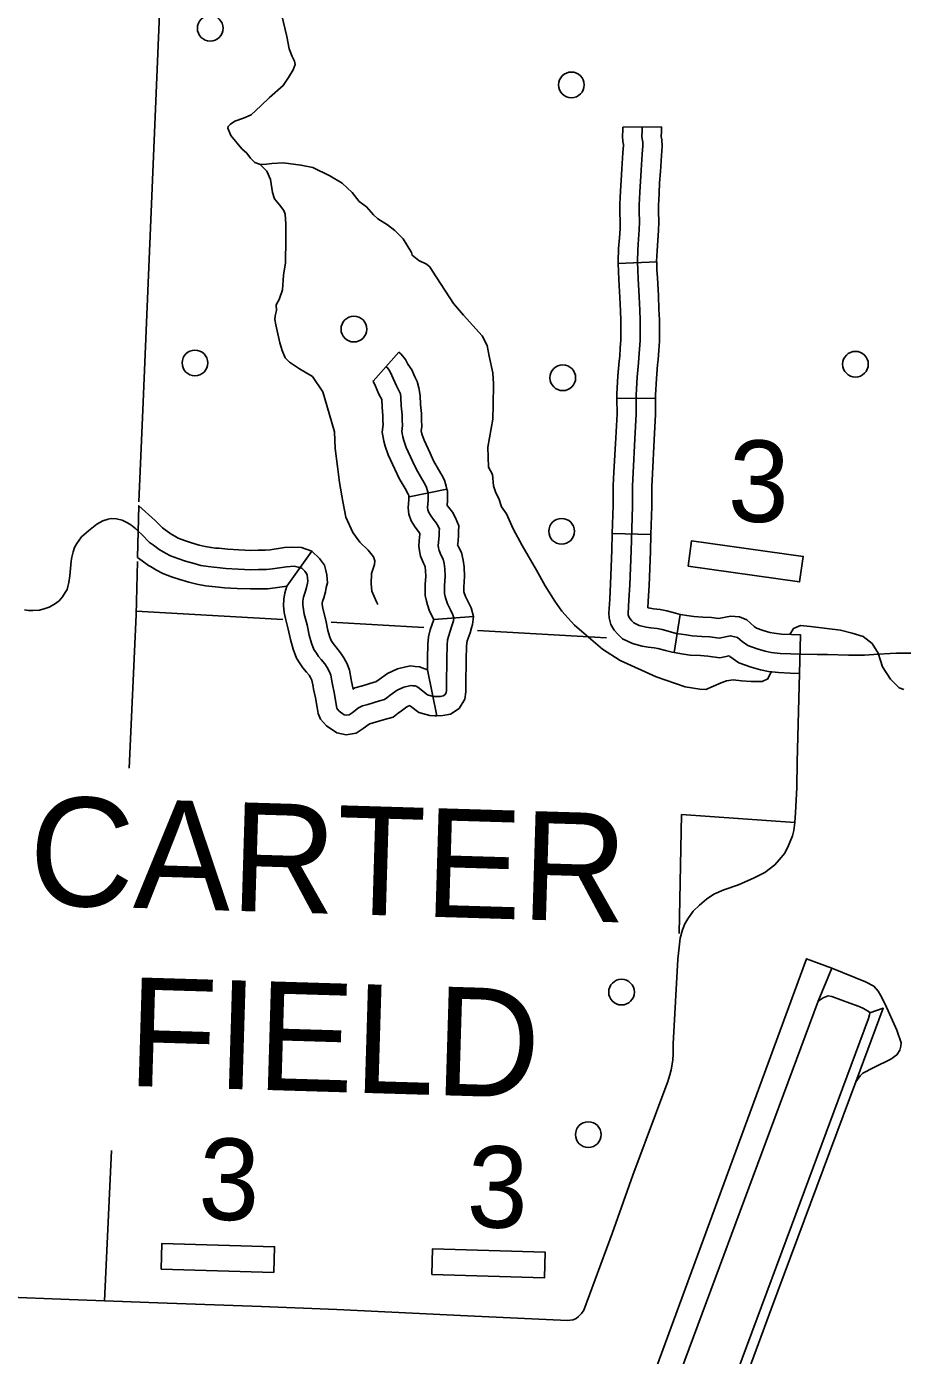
# Model space of a CAD drawing. Extents: x 653372 to 905732, y 627442 to 787275.
# Drawn here: x 689902 to 693304, y 750128 to 755293 of the extents above; entities that cross this region are included whole.
import ezdxf

# ---------------------------------------------------------------- set-up
doc = ezdxf.new("R2010")
doc.units = 0
for name, color, linetype in [('31', 7, 'Continuous'), ('32', 7, 'Continuous'), ('33', 7, 'Continuous'), ('35', 7, 'Continuous'), ('5', 7, 'Continuous'), ('56', 7, 'Continuous'), ('57', 7, 'Continuous'), ('6', 7, 'Continuous')]:
    doc.layers.add(name, color=color, linetype=linetype)

msp = doc.modelspace()

# ---------------------------------------------------------------- linework, layer by layer
at = {"layer": '31'}
msp.add_line((690913.4, 753117.6), (691010.3, 753253.9), dxfattribs=at)
for points in [[(690460.4, 753322.2), (690458.5, 753323.3), (690440.5, 753336.5), (690430, 753344.4), (690402.2, 753372.7), (690338.1, 753430.3), (690333.1, 753229.5)], [(691108.1, 752641.3), (691107.5, 752642.7), (691105.4, 752657.7), (691097.7, 752697.9), (691088.8, 752741.5), (691083.7, 752771.2), (691079, 752784.1), (691069.3, 752801), (691060.8, 752815.3), (691046.5, 752832.3), (691035.8, 752844.5), (691028.1, 752857.1), (691017.9, 752871.9), (691009.3, 752895.9), (691000, 752927.7), (690991.9, 752967.7), (690980.8, 753008.8), (690977.5, 753026.4), (690975.1, 753045.1), (690975.9, 753059.6), (690978.1, 753074.8), (690984.6, 753094.2), (690989.8, 753112.7), (690992.9, 753129.1), (690995.3, 753137.5), (690994, 753150.3), (690991.7, 753160.6), (690990.2, 753166.6), (690983.7, 753175.7), (690971.7, 753187.1), (690957.4, 753191.4), (690941.3, 753194.8), (690911.5, 753193.2), (690857.7, 753185), (690833.8, 753182.3), (690802.8, 753182), (690772.9, 753181.6), (690723.6, 753183.5), (690676.9, 753186.2), (690642.2, 753190.2), (690629.2, 753191), (690608, 753193.4), (690579.7, 753198.5), (690552.7, 753205.2), (690520.2, 753215.1), (690490.4, 753225), (690461.4, 753236), (690442.5, 753245.5), (690417, 753260.7), (690395.8, 753276.3), (690380.4, 753287.8), (690350.3, 753318.5), (690335.6, 753331.7)], [(691010.3, 753253.9), (690970.5, 753267.5), (690932.4, 753269.4), (690903.8, 753267.9), (690847.9, 753259.4), (690829.2, 753257.3), (690801.9, 753257), (690773.9, 753256.6), (690727.2, 753258.4), (690683.4, 753260.9), (690648.9, 753264.9), (690635.6, 753265.8), (690618.8, 753267.6), (690595.5, 753271.8), (690572.8, 753277.5), (690542.9, 753286.6), (690515.5, 753295.6), (690491.7, 753304.7), (690478.7, 753311.3), (690460.4, 753322.2)], [(690383.5, 753193.4), (690375.6, 753198.2), (690351.2, 753216), (690333.1, 753229.5)], [(691010.3, 753253.9), (691040.5, 753225.1), (691059.4, 753198.7), (691064.7, 753177.8), (691068.1, 753162.2), (691071.3, 753130.9), (691066, 753112), (691063, 753095.7), (691056.3, 753072), (691051.4, 753057.4), (691050.6, 753052.1), (691050.4, 753047.7), (691051.6, 753038.1), (691053.9, 753025.5), (691064.9, 752984.9), (691072.9, 752945.7), (691080.6, 752919.1), (691085.2, 752906.4), (691091, 752898), (691096.4, 752889.1), (691103.4, 752881.2), (691122.1, 752858.9), (691134.1, 752838.9), (691147.3, 752815.9), (691156.5, 752790.6), (691162.5, 752755.3), (691164.2, 752747)], [(690913.4, 753117.6), (690867.5, 753110.6), (690838.4, 753107.4), (690803.7, 753107), (690771.9, 753106.6), (690720, 753108.6), (690670.5, 753111.4), (690635.6, 753115.5), (690622.7, 753116.3), (690597.2, 753119.1), (690563.9, 753125.1), (690532.6, 753132.9), (690497.6, 753143.6), (690465.2, 753154.3), (690431, 753167.3), (690406.4, 753179.8), (690383.5, 753193.4)], [(691017.2, 752717.1), (691015.1, 752727.7), (691010.9, 752751.9), (691010.8, 752752.3), (691004.6, 752763.1), (690999.5, 752771.6), (690989.6, 752783.4), (690975.1, 752799.9), (690965.2, 752816.2), (690950.6, 752837.3), (690937.9, 752872.8), (690927.1, 752909.7), (690918.8, 752950.4), (690907.6, 752992.1), (690903.4, 753014.6), (690899.8, 753042.6), (690901.2, 753067.1), (690904.8, 753092.2), (690913.4, 753117.6)], [(691164.2, 752747), (691170.2, 752717.8), (691177.7, 752722.1), (691207, 752730.1), (691252.5, 752744.1), (691258.4, 752745.6), (691271.4, 752754.9), (691304.6, 752778.5), (691343, 752796), (691392.5, 752808.2), (691412, 752805.2), (691429, 752803.8), (691459.1, 752792), (691495.4, 752613.4)], [(691495.4, 752613.4), (691488.6, 752613.4), (691469.1, 752614.5), (691426.3, 752626), (691394, 752650.7), (691391.1, 752653.1), (691379.8, 752648), (691358.7, 752632.9), (691346.2, 752623.9), (691326.1, 752608), (691292.9, 752599.6), (691248.7, 752586), (691235.6, 752582.4), (691233.1, 752581), (691209.5, 752563.7), (691182.2, 752546.1), (691144, 752540), (691106.8, 752547), (691066.9, 752574.7), (691044, 752600.7), (691034.6, 752622.3), (691031.4, 752645.4), (691024.1, 752683.3), (691017.2, 752717.1)], [(691492.6, 752688.3), (691481, 752688.9), (691460.1, 752694.6), (691441.3, 752708.9), (691427.6, 752720.8), (691418.2, 752727.5), (691411.8, 752730), (691403.2, 752730.7), (691395.9, 752731.8), (691367.7, 752724.9), (691342.2, 752713.3), (691315, 752693.9), (691301, 752683.8), (691292.1, 752676.7), (691272.7, 752671.8), (691227.9, 752658), (691206.6, 752652.3), (691192.2, 752644), (691166.9, 752625.5), (691154.7, 752617.6), (691145.1, 752616.1), (691136.4, 752617.7), (691117.1, 752631.1), (691108.1, 752641.3)]]:
    msp.add_lwpolyline(points, dxfattribs=at)
at = {"layer": '32'}
for p, q in [((692218.7, 754901.7), (692368.7, 754902.3)), ((692199.8, 754372.1), (692349.7, 754378.1)), ((691248.4, 753914.8), (691347.6, 754027.4)), ((692195.1, 753847.3), (692345.1, 753848.7)), ((691388, 753464.2), (691534.9, 753494.5)), ((692177.2, 753322.6), (692327.1, 753318.1)), ((691483.7, 752987.6), (691637.7, 752999.6)), ((692418.2, 752859.1), (692441.3, 753007.3))]:
    msp.add_line(p, q, dxfattribs=at)
for points in [[(692218.7, 754901.7), (692218.8, 754890.3), (692216.9, 754866), (692218.4, 754845.5), (692220.7, 754834.2), (692220.9, 754830.3), (692218.7, 754801.4), (692214.9, 754739.6), (692211.5, 754694.2), (692209.8, 754653.7), (692208, 754626.4), (692206.7, 754604.1), (692206.4, 754572.6), (692207.6, 754532.4), (692207.3, 754506.2), (692204.8, 754471), (692202, 754429.7), (692199.5, 754380.1), (692199.8, 754372.1)], [(692293.7, 754902), (692293.8, 754887.6), (692292.1, 754865.8), (692292.8, 754855.8), (692295.4, 754843.4), (692296, 754828.9), (692293.5, 754796.2), (692289.7, 754734.5), (692286.4, 754689.9), (692284.7, 754649.7), (692282.8, 754621.9), (692281.7, 754601.6), (692281.4, 754573.3), (692282.6, 754533), (692282.2, 754503.1), (692279.6, 754465.9), (692276.9, 754425.2), (692274.6, 754379.6), (692276, 754344.3), (692277.5, 754313.2), (692281.9, 754242.6), (692283.8, 754190.9), (692285.6, 754151.1), (692285.3, 754109.4), (692285.2, 754072.1), (692283.2, 754038.2), (692280.7, 754005.2), (692278.6, 753985.2), (692274, 753929.7), (692269.9, 753861.8), (692270.6, 753786.2), (692265.3, 753690.4), (692258.3, 753557.5), (692256.3, 753506.9), (692255.4, 753428.9), (692250.2, 753254.8), (692245.3, 753123.1), (692242, 753063.1), (692239, 753012.5), (692239.3, 753006.6), (692241.5, 752998.5), (692246.2, 752990.5), (692253.4, 752982.3), (692261.2, 752974.6), (692281.2, 752965.1), (692308.6, 752958.3), (692326.4, 752955.3), (692351.6, 752952.5), (692371.3, 752948.5), (692403.8, 752939.5), (692425, 752933.9), (692464.6, 752927.8), (692487.3, 752924.6), (692524.5, 752922.5), (692555.7, 752920.6), (692592.3, 752915.5), (692637, 752924.7), (692663.8, 752918.3), (692681.2, 752902.4), (692703.6, 752886.8), (692740.2, 752874.3), (692770.7, 752865), (692794.9, 752860.3), (692829, 752856.3), (692870.7, 752854.5), (692906.9, 752853.4)], [(692368.7, 754902.3), (692368.8, 754884.9), (692367.4, 754865.9), (692370.1, 754852.5), (692371.1, 754827.6), (692368.3, 754791.1), (692364.5, 754729.3), (692361.2, 754685.5), (692359.5, 754645.6), (692357.7, 754617.4), (692356.7, 754599.1), (692356.4, 754574), (692357.7, 754533.7), (692357.2, 754499.9), (692354.5, 754460.8), (692351.8, 754420.8), (692349.6, 754379.2), (692349.7, 754378.1)], [(692199.8, 754372.1), (692201.1, 754340.9), (692202.6, 754309.1), (692206.9, 754238.9), (692208.8, 754187.8), (692210.6, 754149.6), (692210.3, 754109.7), (692210.2, 754074.5), (692208.3, 754043.2), (692206, 754011.9), (692203.9, 753992.2), (692199.1, 753935), (692194.9, 753863.6), (692195.1, 753847.3)], [(692349.7, 754378.1), (692350.9, 754347.7), (692352.4, 754317.4), (692356.8, 754246.3), (692358.7, 754193.9), (692360.6, 754152.5), (692360.3, 754109), (692360.2, 754069.8), (692358, 754033.1), (692355.4, 753998.5), (692353.3, 753978.1), (692348.8, 753924.3), (692344.9, 753859.9), (692345.1, 753848.7)], [(691347.6, 754027.4), (691357.8, 754018.8), (691373.7, 753998.6), (691383.4, 753980.5), (691398.6, 753958.4), (691410.5, 753931.4), (691418.8, 753912.8), (691426.5, 753888.3), (691431.3, 753858.7), (691432.7, 753823.4), (691435.8, 753788.3), (691436.6, 753764.5), (691437, 753738.4), (691435.2, 753721.6), (691436.5, 753714.3), (691438.7, 753706.3), (691446.3, 753685.4), (691469.5, 753634.7), (691483.1, 753604.9), (691502.2, 753571.6), (691515.3, 753548.9), (691525.7, 753529.7), (691532.5, 753506.2), (691534.9, 753494.5)], [(691299.2, 753970.1), (691303.6, 753966.3), (691310.7, 753957.4), (691315.9, 753947.6), (691325.8, 753925.3), (691338.6, 753896.1), (691349, 753876.1), (691354.2, 753865.4), (691356.5, 753851.2), (691357.8, 753818.6), (691360.9, 753783.7), (691361.6, 753762.6), (691361.9, 753742), (691359.4, 753718.7), (691363.4, 753697.7), (691367.1, 753683.8), (691376.8, 753657), (691401.3, 753603.5), (691416.3, 753570.6), (691437.2, 753534.2), (691449.9, 753512.3), (691455.9, 753501.1), (691459.7, 753488.2), (691461.7, 753478.5), (691461.8, 753452.4), (691460, 753423.9), (691461.1, 753414.7), (691464.9, 753403.6), (691473.2, 753389.6), (691483.3, 753376.9), (691493.5, 753363.8), (691500.9, 753350.7), (691505.6, 753339.1), (691505.3, 753330.9), (691505.3, 753316.2), (691502.2, 753287), (691501.4, 753275.6), (691502.5, 753266.8), (691504.5, 753256.2), (691511.7, 753239), (691520.4, 753222.3), (691524, 753205.7), (691527, 753185), (691528.5, 753156.1), (691526, 753118.4), (691525.1, 753105.6), (691525.6, 753089.6), (691527.9, 753077.1), (691530.9, 753067.9), (691537.2, 753049.4), (691548.4, 753026.1), (691558.3, 753006.6), (691561.6, 752994.1), (691560.4, 752983.2), (691553.2, 752959.1), (691542.2, 752926.4), (691537.5, 752908.7), (691536, 752888.6), (691534.4, 752834.4), (691533.7, 752735.9), (691533, 752712.6), (691531.8, 752703), (691527.5, 752695.8), (691520, 752691), (691509.9, 752689), (691492.6, 752688.3)], [(691248.4, 753914.8), (691248.4, 753914.8), (691257.2, 753895.1), (691271, 753863.6), (691281.8, 753842.9), (691283, 753813.8), (691286, 753779.1), (691286.7, 753760.7), (691286.9, 753745.5), (691283.7, 753715.7), (691290.2, 753681), (691295.4, 753661.3), (691307.3, 753628.5), (691333.1, 753572.3), (691349.6, 753536.2), (691372.2, 753496.8), (691384.4, 753475.6), (691386.1, 753472.5), (691386.8, 753470.2), (691388, 753464.2)], [(692195.1, 753847.3), (692195.6, 753788), (692190.4, 753694.4), (692183.4, 753560.9), (692181.3, 753508.8), (692180.5, 753430.5), (692177.2, 753322.6)], [(692345.1, 753848.7), (692345.7, 753784.5), (692340.2, 753686.3), (692333.2, 753554), (692331.3, 753505), (692330.4, 753427.4), (692327.1, 753318.1)], [(691534.9, 753494.5), (691536.6, 753486.3), (691536.8, 753450.2), (691535.6, 753431.6), (691542.3, 753423.3), (691556.1, 753405.4), (691568.6, 753383.4), (691581, 753352.6), (691580.3, 753329.8), (691580.3, 753312.2), (691576.9, 753280.3), (691576.7, 753277.9), (691579.7, 753270.9), (691591.5, 753247.9), (691597.8, 753219.2), (691601.8, 753192.3), (691603.6, 753155.4), (691600.8, 753113.5), (691600.2, 753104.2), (691600.4, 753097.7), (691600.8, 753095.6), (691602.1, 753091.3), (691606.7, 753077.9), (691615.6, 753059.4), (691628.8, 753033.5), (691637.7, 752999.6), (691634.2, 752968.2), (691630.3, 752955.2)], [(691386.7, 753470.6), (691386.8, 753454.5), (691384.7, 753421.7), (691387.6, 753397.9), (691396.4, 753372), (691411.3, 753346.8), (691424.4, 753330.5), (691430.3, 753322.8), (691430.3, 753320.2), (691427.5, 753293.6), (691426, 753273.4), (691428.4, 753255.2), (691432.2, 753234.5), (691443.8, 753207.2), (691449.2, 753196.6), (691450.2, 753192.2), (691452.3, 753177.7), (691453.3, 753156.7), (691451.1, 753123.4), (691450.1, 753107.1), (691450.7, 753081.5), (691455.1, 753058.7), (691459.6, 753044.5), (691467.6, 753020.9), (691483.7, 752987.6)], [(692177.2, 753322.6), (692175.3, 753257.3), (692170.3, 753126.6), (692167.1, 753067.4), (692163.8, 753012.8), (692164.8, 752994.3), (692171.9, 752969.1), (692185.2, 752946.3), (692198.8, 752930.9), (692217.3, 752912.4), (692255.9, 752894.1), (692293.3, 752884.8), (692316, 752881), (692339.9, 752878.4), (692353.8, 752875.5), (692384.3, 752867.1), (692409.6, 752860.4), (692418.3, 752859.1)], [(692327.1, 753318.1), (692325.2, 753252.2), (692320.2, 753119.6), (692316.9, 753058.8), (692315.4, 753033.9), (692323.9, 753031.8), (692336.7, 753029.6), (692363.3, 753026.7), (692388.9, 753021.4), (692423.4, 753012), (692440.4, 753007.4), (692441.3, 753007.3)], [(691483.7, 752987.6), (691470.3, 752948), (691463.3, 752921.2), (691461.1, 752892.6), (691459.4, 752835.8), (691459.1, 752792)], [(692441.3, 753007.3), (692475.5, 753002), (692494.6, 752999.3), (692528.9, 752997.4), (692563.2, 752995.3), (692589.8, 752991.6), (692638.2, 753001.4), (692671.5, 752998.9), (692700.1, 752986.8), (692728.2, 752961.1), (692737.8, 752954.4), (692763.4, 752945.7), (692788.9, 752937.8), (692806.4, 752934.4), (692835, 752931.1), (692873.4, 752929.5), (692908.1, 752928.4), (692904.2, 752778.5)], [(691630.3, 752955.2), (691624.7, 752936.4), (691614.1, 752904.9), (691611.8, 752896.3), (691610.9, 752884.6), (691609.4, 752833), (691608.7, 752734.5), (691607.9, 752706.8), (691604.2, 752677.9), (691582.7, 752642.2), (691548.5, 752620.1), (691518.6, 752614.3), (691495.4, 752613.4)], [(692418.2, 752859.1), (692453.6, 752853.6), (692480, 752849.9), (692520, 752847.6), (692548.2, 752845.9), (692594.7, 752839.5), (692630.9, 752846.8), (692634.3, 752843.7), (692669.4, 752819.3), (692717.1, 752803), (692752.5, 752792.1), (692783.4, 752786.1), (692823.1, 752781.4), (692868, 752779.6), (692904.2, 752778.5)]]:
    msp.add_lwpolyline(points, dxfattribs=at)
at = {"layer": '33'}
for points in [[(689894.9, 753025.4), (689910.1, 753022.8), (689926.7, 753022.7), (689952.5, 753024.9), (689974.7, 753030.6), (689990.2, 753036.5), (690011.4, 753047.4), (690028.8, 753060.9), (690041.6, 753075.8), (690052.3, 753092.5), (690059.9, 753105), (690063.1, 753115.6), (690066.2, 753132.1), (690069.9, 753157.9), (690075.5, 753215.1), (690078.1, 753230.4), (690082.9, 753250.4), (690088.1, 753267.6), (690097.9, 753283.5), (690116.2, 753309.8), (690142.8, 753333.2), (690175, 753358.2), (690198.3, 753371.1), (690219, 753378.5), (690231.4, 753380.7), (690251.4, 753379.3), (690274.2, 753373.9), (690294.8, 753364.3), (690307.7, 753355.9), (690326.3, 753340), (690335.6, 753331.7)], [(692906.9, 752853.4), (692973.4, 752852.4), (693013.2, 752851.8), (693094.2, 752849.7), (693156.7, 752849.8), (693211, 752852.9), (693256.5, 752855.5), (693281.3, 752857.1), (693309.6, 752857), (693346.5, 752856.7), (693375.2, 752855.9), (693414.8, 752854.3), (693483.9, 752850.6), (693508.6, 752849.9), (693540.5, 752850.5)], [(692611.1, 751936.9), (692667.6, 751956.9), (692728.6, 751983.7), (692769.8, 752004.9), (692808.5, 752034.5), (692825.9, 752053.6), (692847, 752080.3), (692861.1, 752109.9), (692876.9, 752146.6), (692882.5, 752167.4), (692886.9, 752199.4), (692889.4, 752236.5), (692893.8, 752335), (692895.4, 752434.6), (692904.2, 752778)], [(689805.2, 750355.2), (690068, 750345.2), (690412.6, 750332.1), (690815.2, 750317.2), (691107.3, 750305.6), (691615.2, 750281.3), (692003.2, 750263.3), (692024.9, 750266.2), (692037, 750270.7), (692046.3, 750278.8), (692057.8, 750290.4), (692066.6, 750303.4), (692176.3, 750601.8), (692256.6, 750827.6), (692349.4, 751074), (692392.8, 751192.4), (692400.6, 751218.1), (692406.1, 751238.2), (692410.2, 751259.1), (692412.8, 751276.5), (692413.5, 751298.9), (692414, 751338.7), (692432.3, 751667.9), (692440.3, 751748.8), (692449.7, 751781.4), (692459.5, 751804.9), (692471.3, 751824.9), (692491, 751853.7), (692515.5, 751878.1), (692542.8, 751901.1), (692572.1, 751920.5), (692611.1, 751936.9)]]:
    msp.add_lwpolyline(points, dxfattribs=at)
at = {"layer": '35'}
for points in [[(690893.6, 755335.6), (690913.3, 755254.6), (690922.8, 755206.2), (690933.8, 755176.7), (690942.7, 755158.3), (690945.4, 755144.8), (690937.7, 755123.8), (690920.3, 755094.3), (690899.6, 755063.4), (690846.2, 755016.5), (690812.1, 754984.4), (690774.8, 754950.1), (690744.5, 754936), (690711.8, 754925.1), (690694.1, 754913.8), (690685.2, 754904.6), (690683.4, 754897.6), (690696, 754869.6), (690737.8, 754817.9), (690757.7, 754800), (690772.1, 754780.6), (690789, 754764.3), (690806.9, 754758.3), (690823.4, 754756.2), (690855.1, 754760.8), (690900.8, 754762.5), (690967.6, 754754.2), (691014.6, 754744.9), (691080.6, 754712.2), (691128.7, 754684.1), (691167, 754647.5), (691193.5, 754612.8), (691222.1, 754592.2), (691249.5, 754561.4), (691266, 754544.7), (691304.8, 754521.5), (691333.3, 754500.1), (691365.4, 754467.6), (691396.9, 754413.9), (691400.5, 754403.5), (691425.9, 754383), (691455.5, 754368.7), (691469.2, 754358.1)], [(690810.8, 754754.6), (690835.4, 754730.8), (690850, 754697.6), (690858.1, 754647.6), (690864.8, 754622.9), (690884.2, 754599.2), (690901.4, 754577.9), (690906.1, 754563.7), (690908.7, 754524.2), (690909.9, 754466.7), (690907.9, 754373.9), (690899.8, 754326.5), (690895.8, 754269.4), (690882.8, 754231.2), (690871.8, 754210.7), (690872.6, 754189.1), (690868.3, 754168.4), (690866.4, 754154.4), (690870.2, 754133.4), (690885.9, 754063.1), (690894.7, 754033.1), (690906.5, 754005.3), (690923, 753988.4), (690962.1, 753961.7), (691013.3, 753932)], [(691469.2, 754358.1), (691478.4, 754341.6), (691560, 754216.1), (691599.6, 754170.5), (691672.5, 754090.5), (691691.5, 754053.5), (691699, 754011.8), (691713.4, 753947.3), (691715.9, 753904.5), (691714.7, 753821.7), (691713, 753766.5), (691693.4, 753657.8), (691696.1, 753579.8), (691711.6, 753551.7), (691715.3, 753507.6), (691724.5, 753479.7), (691736.4, 753458), (691747.2, 753426.4), (691765.9, 753398.5), (691792.2, 753339.8), (691826.7, 753276), (691883.1, 753180.3), (691916.4, 753119), (691953.9, 753059.5), (691981.8, 753020), (692030.5, 752966.3), (692139.1, 752873.1), (692208.1, 752828.1), (692347.4, 752764.6)], [(691013.3, 753932), (691053.1, 753872.8), (691078, 753788.1), (691098.2, 753717.6), (691101.5, 753652.8), (691109.8, 753583), (691117.5, 753520.3), (691130.2, 753447.1), (691142.5, 753385.1), (691169.7, 753326.3), (691196.8, 753288.3), (691228.5, 753257.6), (691250, 753231.4), (691254.8, 753216.4), (691254.3, 753201.6), (691241.4, 753166.3), (691240.2, 753126.2), (691243.8, 753097.8), (691261.1, 753056.4), (691266.8, 753046.4)], [(692866.6, 752929.7), (692881.2, 752953), (692907.9, 752964.9), (692947.1, 752960.9), (693063.2, 752946.9), (693109.3, 752934.4), (693151.9, 752921.4), (693186.3, 752895), (693209.8, 752857)], [(693209.8, 752857), (693219.4, 752828), (693226.4, 752804.5), (693258, 752755.8)], [(692347.4, 752764.6), (692460.7, 752725.7), (692517.4, 752716.9), (692540.1, 752715.4)], [(692540.1, 752715.4), (692600, 752741.2), (692621, 752750), (692646.2, 752753.6), (692678.8, 752750.1), (692716.3, 752747.1), (692759.7, 752747.5), (692781.5, 752757.6), (692794.4, 752784)], [(693258, 752755.8), (693291.4, 752722.5), (693310, 752716.2)]]:
    msp.add_lwpolyline(points, dxfattribs=at)
at = {"layer": '5'}
for points in [[(690897.6, 752987.9), (690328.4, 753020.4)], [(691445.8, 752956.7), (691085.3, 752977.2)], [(692154.2, 752916.3), (691653.4, 752944.8)]]:
    msp.add_lwpolyline(points, dxfattribs=at)
at = {"layer": '56'}
for points in [[(692471.6, 753195.2), (692485.5, 753294.3), (692918.8, 753233.2), (692904.8, 753134.2)], [(690425.2, 750463.2), (690428.2, 750563.2), (690865.6, 750550.1), (690862.5, 750450.1)], [(691476.4, 750442), (691479.4, 750541.9), (691916.7, 750528.8), (691913.7, 750428.8)]]:
    msp.add_lwpolyline(points, close=True, dxfattribs=at)
for centre in [(690615.6, 755285.8), (692018.4, 755066), (691173.7, 754116.8), (690556.4, 753985.2), (693121.7, 753980.2), (691985, 753927.6), (691980.6, 753330.9), (692213.3, 751539.7), (692084.2, 750985.8)]:
    msp.add_circle(centre, 50, dxfattribs=at)
at = {"layer": '57'}
msp.add_line((693229.7, 751477.2), (693177.2, 751459.3), dxfattribs=at)
for points in [[(693030.5, 751632.9), (692932.1, 751669.5), (692336.1, 750046.6), (692198.7, 749679.9), (691739.6, 748445.1), (691608.1, 748093.3), (691575.9, 748000.7), (691535.7, 747887.3), (690925.2, 746243.9), (690846.5, 746032.7)], [(690846.5, 746032.7), (690937.7, 745999.2), (690971.2, 746089), (691615.8, 747837.2), (691685.2, 748023.2), (692230.2, 749493.5), (692274.4, 749610), (692977.4, 751504.3), (693030.5, 751632.9)], [(693099.7, 751496.5), (693029.9, 751522.2), (693015.3, 751525), (692995.7, 751517.5), (692977.4, 751504.3), (693030.5, 751632.9), (693160.6, 751579.9), (693192.5, 751562.7), (693210.6, 751543.5), (693219.1, 751527.8), (693236.7, 751493.2), (693283.1, 751391.2)], [(693177.2, 751459.3), (693176, 751451.8), (693172.6, 751437.5), (692873.3, 750631.1), (692565.4, 749802)], [(692607.6, 749800.5), (692796, 750311.2), (693123, 751191.6), (693229.7, 751477.2)], [(693283.1, 751391.2), (693299.5, 751342.1), (693298.3, 751329.1), (693294.6, 751314.6), (693282.7, 751296.3), (693258.6, 751279.1), (693193.6, 751247), (693150.7, 751224.8), (693139.9, 751213.8), (693123, 751191.6), (693229.7, 751477.2), (693177.2, 751459.3), (693174.9, 751463.3), (693153.4, 751475.8), (693135.8, 751483.3), (693099.7, 751496.5)]]:
    msp.add_lwpolyline(points, dxfattribs=at)
at = {"layer": '6'}
for points in [[(692080.4, 757784.9), (692441.9, 757772.9), (692336.5, 755499.6), (690429.1, 755614.1), (690424.7, 755497.3), (690354.2, 753803.5), (690338.7, 753445.3)], [(690332.7, 753213.6), (690327.8, 753006.4), (690301, 752409.5)], [(692437.1, 751767.2), (692446.5, 752229.9), (692886.9, 752199.4)], [(690232.6, 750924.1), (690205, 750340)]]:
    msp.add_lwpolyline(points, dxfattribs=at)

# ---------------------------------------------------------------- texts
at = {"layer": '56'}
for p in [(692624, 753370.7), (690567, 750657.4), (691609.6, 750627.5)]:
    msp.add_text('3', height=316.8, rotation=358.28, dxfattribs=at).set_placement(p)
at = {"layer": '57'}
for s, p in [('CARTER', (689907, 751879.7)), ('FIELD', (690291.1, 751175.6))]:
    msp.add_text(s, height=422.4, rotation=358.28, dxfattribs=at).set_placement(p)

doc.saveas('drawing.dxf')
